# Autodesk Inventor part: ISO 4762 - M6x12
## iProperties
Created: 2007-08
Part Number: ISO 4762 - M6x12
Material: Stahl, weich, unlegiert
Description: Innensechskantschraube
Vendor: Autodesk Inc.
Document SubType Name: Modeling
Standard: ISO 4762
Designer: Ulrich
Standards Organization: ISO
Language: de-DE
Size Designation: M6 x 12
Categories: <MemberInstance Version="R10.0.0"><Categories><Category DisplayName="Schrauben" InternalName="e4da775c-781d-43d5-af7c-5136215cf5a6" Mnemonic="FSTN"><Category Di
Author: Ulrich
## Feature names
1. Körper [Revolution]
2. Loch [Extrusion]
3. Rundung1 [Fillet]
4. Fase1 [Chamfer]
